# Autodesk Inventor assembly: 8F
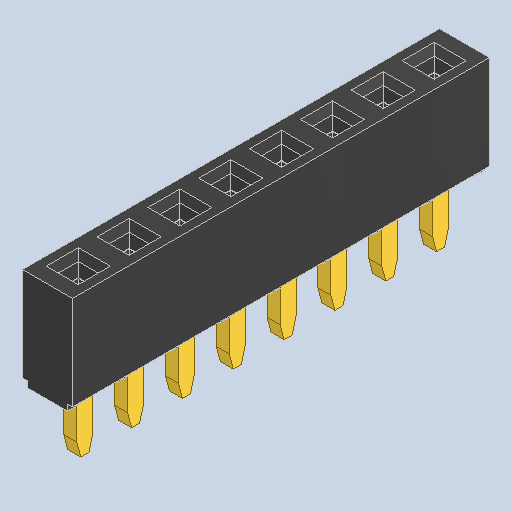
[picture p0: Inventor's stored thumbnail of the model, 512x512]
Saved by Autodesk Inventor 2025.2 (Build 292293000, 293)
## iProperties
Created: 2025-04
Part Number: 8F
Description: PART--DESC
Document SubType Name: Assembly
Designer: BennF
Author: BennF
Revision Number: NONE
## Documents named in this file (3)
- C:\Users\BennF\Nextcloud\Benutzer\CNC JarBeRi\existing parts\Electronics\RepRap A4988 Shied (USE WITHOUT ARDUINO)\reprap-a4988-1.snapshot.1\RepRap\RepRap\8F.iam
- C:\Users\BennF\Nextcloud\Benutzer\CNC JarBeRi\existing parts\Electronics\RepRap A4988 Shied (USE WITHOUT ARDUINO)\reprap-a4988-1.snapshot.1\RepRap\RepRap\8F Geometry.ipt
- C:\Users\BennF\Nextcloud\Benutzer\CNC JarBeRi\existing parts\Electronics\RepRap A4988 Shied (USE WITHOUT ARDUINO)\reprap-a4988-1.snapshot.1\RepRap\RepRap\Pin3.ipt
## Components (2 placed, 2 different names)
1. 8F Geometry
2. Pin3
